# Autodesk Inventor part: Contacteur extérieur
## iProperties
Created: 2002-05
Part Number: Contacteur extérieur
Material: Par défaut
Document SubType Name: Modélisation
Designer: Flavien MARTY
Control State: 0
Master: False
Checked Out: False
Shininess: 20.0
Length Units: 11269
Angle Units: 11279
Time Units: 11290
Mass Units: 11283
Length Display Precision: 3
Angle Display Precision: 2
Compacted: True
Density: 0.0
Volumn: 0.0
Area: 0.0
PropertySet Name: Model Information
Author: Flavien MARTY
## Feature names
1. Extrusion1
2. Extrusion2
3. Congé1 [Fillet]
4. Réseau rectangulaire1 [Rectangular Pattern]
5. Extrusion3
6. Congé2 [Fillet]
7. Perçage1 [Hole]
